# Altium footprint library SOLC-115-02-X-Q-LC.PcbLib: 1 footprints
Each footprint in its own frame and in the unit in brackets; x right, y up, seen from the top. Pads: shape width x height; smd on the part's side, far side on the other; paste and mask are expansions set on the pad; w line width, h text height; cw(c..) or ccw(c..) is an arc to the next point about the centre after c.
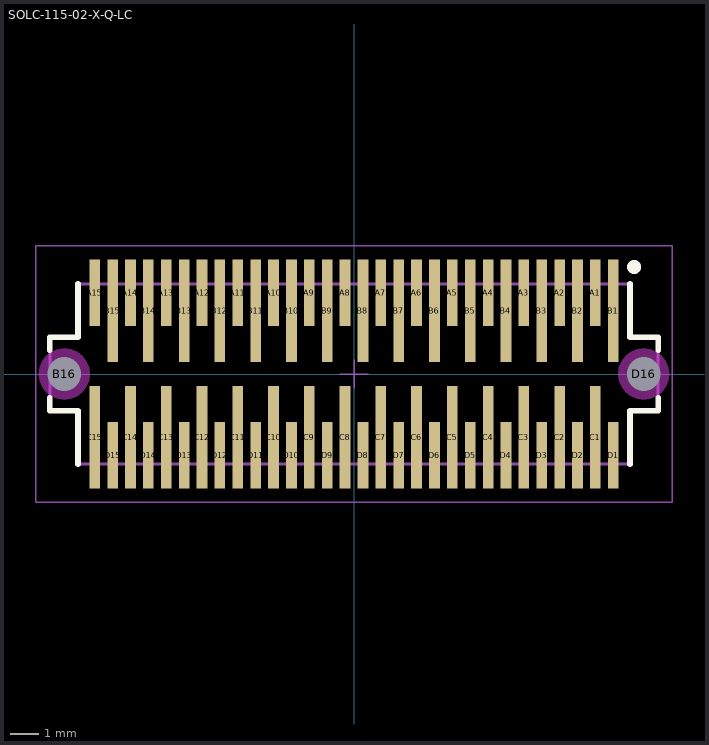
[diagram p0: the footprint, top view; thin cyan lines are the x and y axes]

## SOLC-115-02-X-Q-LC [mm] "1.27mm pitch, 60 pin,  socket strip; 4 rows, w/locking clips, SMT"
height 4.62
pads (62):
  rect 0.38x2.36 smd mask+0: A1(8.572,2.885) A2(7.302,2.885) A3(6.032,2.885) A4(4.763,2.885) A5(3.492,2.885) A6(2.222,2.885) A7(0.953,2.885) A8(-0.318,2.885) A9(-1.587,2.885) A10(-2.857,2.885) A11(-4.127,2.885) A12(-5.397,2.885) A13(-6.667,2.885) A14(-7.938,2.885) A15(-9.207,2.885) D1(9.207,-2.885) D2(7.938,-2.885) D3(6.667,-2.885) D4(5.397,-2.885) D5(4.127,-2.885) D6(2.857,-2.885) D7(1.587,-2.885) D8(0.318,-2.885) D9(-0.953,-2.885) D10(-2.222,-2.885) D11(-3.492,-2.885) D12(-4.763,-2.885) D13(-6.032,-2.885) D14(-7.302,-2.885) D15(-8.572,-2.885)
  rect 0.38x3.63 smd mask+0: B1(9.207,2.25) B2(7.938,2.25) B3(6.667,2.25) B4(5.397,2.25) B5(4.127,2.25) B6(2.857,2.25) B7(1.587,2.25) B8(0.318,2.25) B9(-0.953,2.25) B10(-2.222,2.25) B11(-3.492,2.25) B12(-4.763,2.25) B13(-6.032,2.25) B14(-7.302,2.25) B15(-8.572,2.25) C1(8.572,-2.25) C2(7.302,-2.25) C3(6.032,-2.25) C4(4.763,-2.25) C5(3.492,-2.25) C6(2.222,-2.25) C7(0.953,-2.25) C8(-0.318,-2.25) C9(-1.587,-2.25) C10(-2.857,-2.25) C11(-4.127,-2.25) C12(-5.397,-2.25) C13(-6.667,-2.25) C14(-7.938,-2.25) C15(-9.207,-2.25)
  round 1 hole 1.2 unplated mask+0: B16(-10.287,0) D16(10.287,0)
Top Overlay:
  circle w0.25: c9.95,3.8 r0.125
  lines w0.2: -10.8,-0.85 -10.8,-1.3 -9.8,-1.3 -9.8,-3.2 ; -10.8,0.85 -10.8,1.3 -9.8,1.3 -9.8,3.2 ; 9.8,-3.2 9.8,-1.3 10.8,-1.3 10.8,-0.85 ; 9.8,3.2 9.8,1.3 10.8,1.3 10.8,0.85
Keep-Out Layer:
  pour cut-out: -9.379,0 -9.41,0.235 -9.501,0.454 -9.645,0.642 -9.833,0.786 -10.052,0.877 -10.287,0.908 -10.522,0.877 -10.741,0.786 -10.929,0.642 -11.073,0.454 -11.164,0.235 -11.195,0 -11.164,-0.235 -11.073,-0.454 -10.929,-0.642 -10.741,-0.786 -10.522,-0.877 -10.287,-0.908 -10.052,-0.877 -9.833,-0.786 -9.645,-0.642 -9.501,-0.454 -9.41,-0.235
  pour cut-out: 11.195,0 11.164,0.235 11.073,0.454 10.929,0.642 10.741,0.786 10.522,0.877 10.287,0.908 10.052,0.877 9.833,0.786 9.645,0.642 9.501,0.454 9.41,0.235 9.379,0 9.41,-0.235 9.501,-0.454 9.645,-0.642 9.833,-0.786 10.052,-0.877 10.287,-0.908 10.522,-0.877 10.741,-0.786 10.929,-0.642 11.073,-0.454 11.164,-0.235
Mechanical 12:
  lines w0.001: -10.8,-1.3 -9.8,-1.3 -9.8,-3.2 9.8,-3.2 9.8,-1.3 10.8,-1.3 10.8,1.3 9.8,1.3 9.8,3.2 -9.8,3.2 -9.8,1.3 -10.8,1.3 -10.8,-1.3
Mechanical 13:
  lines w0.1: -10.8,-1.3 -9.8,-1.3 -9.8,-3.2 9.8,-3.2 9.8,-1.3 10.8,-1.3 10.8,1.3 9.8,1.3 9.8,3.2 -9.8,3.2 -9.8,1.3 -10.8,1.3 -10.8,-1.3
  text ".Designator" at 0,-0.127 h1.52
Mechanical 15:
  lines w0.05: -0.5,0 0.5,0 ; 0,-0.5 0,0.5 ; -11.3,-4.55 11.3,-4.55 11.3,4.55 -11.3,4.55 -11.3,-4.55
